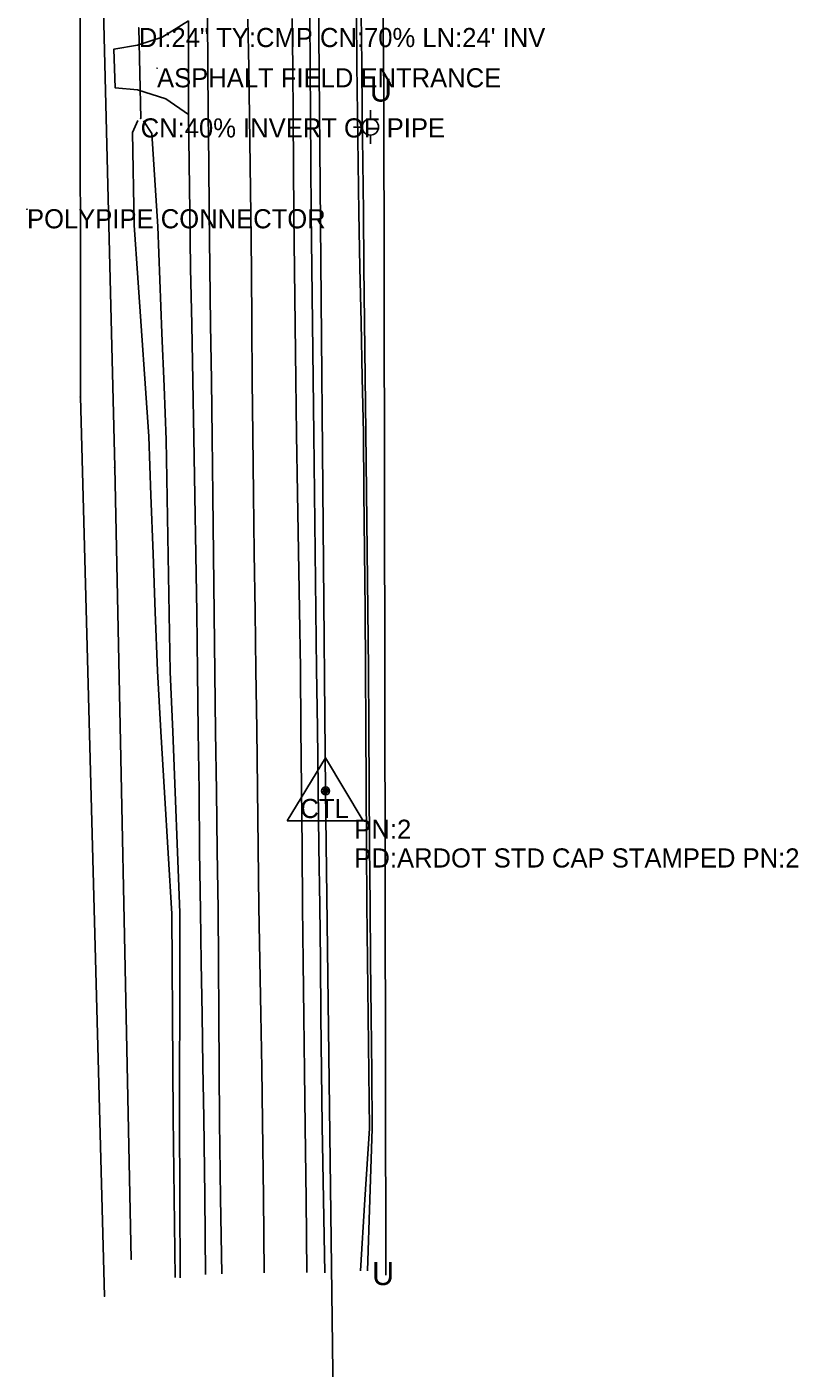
# Model space of a CAD drawing. Extents: x 1804576 to 1805329, y 515859 to 519427.
# Drawn here: x 1804901 to 1805102.5, y 516699.2 to 517049.7 of the extents above; entities that cross this region are included whole.
import ezdxf

# ---------------------------------------------------------------- set-up
doc = ezdxf.new("R2010")
doc.units = 0
for name, color, linetype in [('Default', 7, 'Continuous'), ('S_BASELINE', 7, 'Continuous'), ('S_DITCHLINE', 7, 'Continuous'), ('S_DRG_PT_SYM', 7, 'Continuous'), ('S_EDGE_PAVEMENT', 7, 'Continuous'), ('S_FIBER_OPTIC_CABLE', 7, 'Continuous'), ('S_GAS_UTILITIES', 7, 'Continuous'), ('S_MSC_PT_SYM', 7, 'Continuous'), ('S_PAVEMENT_CROWN', 7, 'Continuous'), ('S_PRIMARY_CTL', 7, 'Continuous'), ('S_PRIMARY_CTL_ANNOT', 7, 'Continuous'), ('S_SHOULDER', 7, 'Continuous'), ('S_SIDE_DRAIN', 7, 'Continuous'), ('S_SIDE_DRAIN_ANNOT', 7, 'Continuous'), ('S_SURVEY_TEXT_ANNOT', 7, 'Continuous'), ('S_UTILITY_POLE', 7, 'Continuous'), ('S_UTL_PT_SYM', 7, 'Continuous')]:
    doc.layers.add(name, color=color, linetype=linetype)

msp = doc.modelspace()

# ---------------------------------------------------------------- linework, layer by layer
at = {"layer": 'S_BASELINE'}
for p, q in [((1804979.02, 516850.02), (1804971.48, 517701.71)), ((1804991.19, 515878.86), (1804979.02, 516850.02))]:
    msp.add_line(p, q, dxfattribs=at)
at = {"layer": 'S_DITCHLINE'}
for points in [[(1804987.04, 517052.77), (1804987.19, 517039.87), (1804987.35, 517026.98), (1804987.5, 517014.09), (1804987.66, 517001.2), (1804987.97, 516986.8), (1804988.27, 516972.41), (1804988.58, 516958.01), (1804988.89, 516943.62), (1804989.03, 516928.18), (1804989.17, 516912.74), (1804989.31, 516897.3), (1804989.44, 516881.86), (1804989.53, 516866.48), (1804989.62, 516851.09), (1804989.71, 516835.71), (1804989.79, 516820.32), (1804989.96, 516805.69), (1804990.12, 516791.06), (1804990.28, 516776.43), (1804990.45, 516761.8), (1804989.29, 516743.23), (1804988.13, 516724.66)], [(1804988.3, 517052.99), (1804988.44, 517040.08), (1804988.59, 517027.17), (1804988.74, 517014.26), (1804988.88, 517001.35), (1804989.03, 516986.96), (1804989.18, 516972.57), (1804989.34, 516958.18), (1804989.49, 516943.78), (1804989.67, 516928.31), (1804989.84, 516912.84), (1804990.02, 516897.37), (1804990.2, 516881.89), (1804990.31, 516866.49), (1804990.41, 516851.09), (1804990.51, 516835.69), (1804990.62, 516820.28), (1804990.76, 516805.68), (1804990.91, 516791.07), (1804991.05, 516776.47), (1804991.2, 516761.86), (1804990.59, 516743.24), (1804989.98, 516724.62)], [(1804929.96, 517025.18), (1804928.57, 517022.06), (1804929.04, 516997.91), (1804929.98, 516984.1), (1804930.92, 516970.29), (1804931.86, 516956.48), (1804932.8, 516942.67), (1804933.37, 516927.35), (1804933.93, 516912.03), (1804934.5, 516896.72), (1804935.06, 516881.4), (1804936.01, 516865.53), (1804936.95, 516849.66), (1804937.9, 516833.79), (1804938.84, 516817.91), (1804938.92, 516804.62), (1804939, 516791.32), (1804939.08, 516778.03), (1804939.16, 516764.73), (1804939.43, 516743.81), (1804939.69, 516722.88)], [(1804931.42, 517025.09), (1804933.59, 517021.81), (1804935.21, 516997.55), (1804935.74, 516983.62), (1804936.27, 516969.68), (1804936.8, 516955.75), (1804937.34, 516941.81), (1804937.61, 516926.66), (1804937.89, 516911.5), (1804938.16, 516896.34), (1804938.44, 516881.18), (1804939.07, 516865.46), (1804939.7, 516849.74), (1804940.33, 516834.02), (1804940.96, 516818.3), (1804940.93, 516804.88), (1804940.91, 516791.47), (1804940.88, 516778.06), (1804940.86, 516764.65), (1804940.95, 516743.72), (1804941.03, 516722.79)]]:
    msp.add_lwpolyline(points, dxfattribs=at)
at = {"layer": 'S_DRG_PT_SYM'}
for points in [[(1804930.21, 517049.4), (1804930.21, 517049.45), (1804930.21, 517049.4), (1804930.16, 517049.4), (1804930.21, 517049.4), (1804930.21, 517049.35), (1804930.21, 517049.4), (1804930.26, 517049.4)], [(1804930.7, 517025.78), (1804930.7, 517025.83), (1804930.7, 517025.78), (1804930.65, 517025.78), (1804930.7, 517025.78), (1804930.7, 517025.73), (1804930.7, 517025.78), (1804930.75, 517025.78)]]:
    msp.add_lwpolyline(points, dxfattribs=at)
at = {"layer": 'S_EDGE_PAVEMENT'}
for points in [[(1804948.13, 517052.08), (1804948.25, 517039.44), (1804948.36, 517026.8), (1804948.47, 517014.16), (1804948.59, 517001.53), (1804948.78, 516986.77), (1804948.97, 516972.02), (1804949.16, 516957.26), (1804949.36, 516942.51), (1804949.53, 516927.11), (1804949.7, 516911.71), (1804949.87, 516896.32), (1804950.04, 516880.92), (1804950.26, 516865.45), (1804950.49, 516849.97), (1804950.71, 516834.5), (1804950.93, 516819.02), (1804951.03, 516805.16), (1804951.13, 516791.29), (1804951.22, 516777.43), (1804951.32, 516763.56), (1804951.59, 516743.69), (1804951.86, 516723.82)], [(1804970.3, 517051.86), (1804970.41, 517039.04), (1804970.51, 517026.21), (1804970.61, 517013.39), (1804970.71, 517000.56), (1804970.89, 516986.2), (1804971.06, 516971.85), (1804971.23, 516957.49), (1804971.4, 516943.14), (1804971.66, 516927.86), (1804971.92, 516912.59), (1804972.17, 516897.32), (1804972.43, 516882.05), (1804972.58, 516866.46), (1804972.72, 516850.86), (1804972.87, 516835.26), (1804973.01, 516819.67), (1804973.18, 516805.35), (1804973.35, 516791.03), (1804973.51, 516776.71), (1804973.68, 516762.39), (1804973.9, 516743.3), (1804974.13, 516724.22)], [(1804943.19, 517051.24), (1804936.33, 517046.95), (1804929.88, 517044.94), (1804923.67, 517043.82), (1804924.05, 517033.71), (1804929.87, 517033.23), (1804937.27, 517030.91), (1804943.17, 517026.81)]]:
    msp.add_lwpolyline(points, dxfattribs=at)
at = {"layer": 'S_FIBER_OPTIC_CABLE'}
for p, q in [((1804991.59, 517309.83), (1804994.19, 517032.71)), ((1804919.59, 517109.13), (1804923.91, 516934.6)), ((1804994.19, 517032.71), (1804994.75, 516723.46)), ((1804923.91, 516934.6), (1804928.26, 516727.68))]:
    msp.add_line(p, q, dxfattribs=at)
at = {"layer": 'S_GAS_UTILITIES'}
for p, q in [((1804914.92, 517321.69), (1804914.94, 516952.97)), ((1804914.94, 516952.97), (1804921.27, 516717.98))]:
    msp.add_line(p, q, dxfattribs=at)
at = {"layer": 'S_MSC_PT_SYM'}
for points in [[(1804934.98, 517038.88), (1804934.98, 517038.93), (1804934.98, 517038.88), (1804934.93, 517038.88), (1804934.98, 517038.88), (1804934.98, 517038.83), (1804934.98, 517038.88), (1804935.03, 517038.88)], [(1804901.01, 517002.04), (1804901.01, 517002.09), (1804901.01, 517002.04), (1804900.96, 517002.04), (1804901.01, 517002.04), (1804901.01, 517001.99), (1804901.01, 517002.04), (1804901.06, 517002.04)]]:
    msp.add_lwpolyline(points, dxfattribs=at)
at = {"layer": 'S_PAVEMENT_CROWN'}
msp.add_lwpolyline([(1804958.72, 517051.72), (1804958.92, 517038.95), (1804959.12, 517026.19), (1804959.32, 517013.42), (1804959.52, 517000.65), (1804959.63, 516986.23), (1804959.74, 516971.81), (1804959.86, 516957.39), (1804959.97, 516942.96), (1804960.18, 516927.62), (1804960.39, 516912.28), (1804960.6, 516896.94), (1804960.81, 516881.6), (1804961.01, 516866.14), (1804961.2, 516850.67), (1804961.39, 516835.21), (1804961.59, 516819.75), (1804961.83, 516805.71), (1804962.08, 516791.67), (1804962.33, 516777.63), (1804962.57, 516763.59), (1804962.76, 516743.86), (1804962.96, 516724.13)], dxfattribs=at)
at = {"layer": 'S_PRIMARY_CTL'}
for p, q in [((1804979.02, 516858.72), (1804968.98, 516842.21)), ((1804979.02, 516858.72), (1804988.84, 516842.21)), ((1804968.98, 516842.21), (1804988.84, 516842.21))]:
    msp.add_line(p, q, dxfattribs=at)
for radius in [1.04, 0.609, 0.344]:
    msp.add_circle((1804979.02, 516850.02), radius, dxfattribs=at)
at = {"layer": 'S_SHOULDER'}
for points in [[(1804974.87, 517052.01), (1804974.95, 517039.31), (1804975.04, 517026.62), (1804975.13, 517013.92), (1804975.22, 517001.22), (1804975.39, 516986.72), (1804975.56, 516972.22), (1804975.73, 516957.72), (1804975.9, 516943.21), (1804976.09, 516927.87), (1804976.28, 516912.53), (1804976.47, 516897.18), (1804976.66, 516881.84), (1804976.87, 516866.39), (1804977.08, 516850.94), (1804977.28, 516835.49), (1804977.49, 516820.04), (1804977.65, 516805.66), (1804977.8, 516791.27), (1804977.96, 516776.89), (1804978.11, 516762.51), (1804978.48, 516743.31), (1804978.85, 516724.1)], [(1804943.19, 517051.28), (1804943.17, 517026.78), (1804943.33, 517014.1), (1804943.5, 517001.41), (1804943.76, 516986.66), (1804944.03, 516971.9), (1804944.29, 516957.15), (1804944.55, 516942.4), (1804944.81, 516927.11), (1804945.07, 516911.83), (1804945.33, 516896.54), (1804945.58, 516881.26), (1804945.76, 516865.61), (1804945.94, 516849.96), (1804946.11, 516834.31), (1804946.29, 516818.66), (1804946.52, 516805.14), (1804946.75, 516791.62), (1804946.98, 516778.11), (1804947.22, 516764.59), (1804947.42, 516744.15), (1804947.62, 516723.71)]]:
    msp.add_lwpolyline(points, dxfattribs=at)
at = {"layer": 'S_SIDE_DRAIN'}
msp.add_line((1804930.21, 517049.4), (1804930.7, 517025.78), dxfattribs=at)
at = {"layer": 'S_UTILITY_POLE'}
for p, q in [((1804990.7, 517025.63), (1804990.7, 517027.88)), ((1804988.61, 517023.5), (1804986.29, 517023.5)), ((1804990.78, 517019.08), (1804990.78, 517021.41))]:
    msp.add_line(p, q, dxfattribs=at)
msp.add_circle((1804990.71, 517023.52), 2.13, dxfattribs=at)
at = {"layer": 'S_UTL_PT_SYM'}
for points in [[(1804914.94, 516952.97), (1804914.94, 516953.02), (1804914.94, 516952.97), (1804914.89, 516952.97), (1804914.94, 516952.97), (1804914.94, 516952.92), (1804914.94, 516952.97), (1804914.99, 516952.97)], [(1804923.91, 516934.6), (1804923.91, 516934.65), (1804923.91, 516934.6), (1804923.86, 516934.6), (1804923.91, 516934.6), (1804923.91, 516934.55), (1804923.91, 516934.6), (1804923.96, 516934.6)], [(1804928.26, 516727.68), (1804928.26, 516727.73), (1804928.26, 516727.68), (1804928.21, 516727.68), (1804928.26, 516727.68), (1804928.26, 516727.63), (1804928.26, 516727.68), (1804928.31, 516727.68)], [(1804921.27, 516717.98), (1804921.27, 516718.03), (1804921.27, 516717.98), (1804921.22, 516717.98), (1804921.27, 516717.98), (1804921.27, 516717.93), (1804921.27, 516717.98), (1804921.32, 516717.98)]]:
    msp.add_lwpolyline(points, dxfattribs=at)

# ---------------------------------------------------------------- texts
at = {"layer": 'Default'}
for p in [(1804990.56, 517030.16), (1804991.12, 516720.91)]:
    msp.add_text('U', height=6, dxfattribs=at).set_placement(p)
at = {"layer": 'S_PRIMARY_CTL'}
msp.add_text('CTL', height=5, dxfattribs=at).set_placement((1804972.43, 516842.95))
at = {"layer": 'S_PRIMARY_CTL_ANNOT'}
for s, p in [('PN:2', (1804986.52, 516837.52)), ('PD:ARDOT STD CAP STAMPED PN:2', (1804986.52, 516830.02))]:
    msp.add_text(s, height=5, dxfattribs=at).set_placement(p)
at = {"layer": 'S_SIDE_DRAIN_ANNOT'}
for s, p in [('DI:24" TY:CMP CN:70% LN:24\' INV', (1804930.21, 517044.4)), ('CN:40% INVERT OF PIPE', (1804930.7, 517020.78))]:
    msp.add_text(s, height=5, dxfattribs=at).set_placement(p)
at = {"layer": 'S_SURVEY_TEXT_ANNOT'}
for s, p in [('ASPHALT FIELD ENTRANCE', (1804934.98, 517033.88)), ('POLYPIPE CONNECTOR', (1804901.01, 516997.04))]:
    msp.add_text(s, height=5, dxfattribs=at).set_placement(p)

doc.saveas('drawing.dxf')
